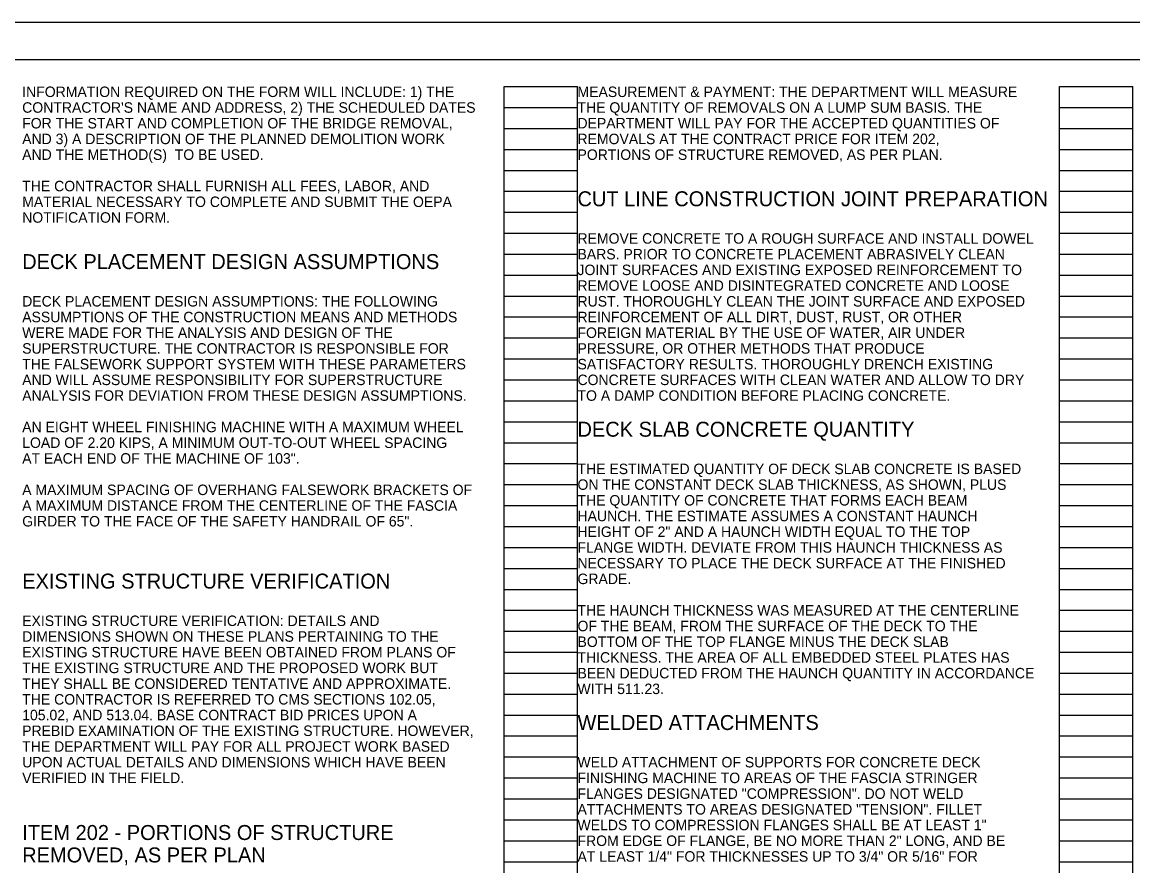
# Model space of a CAD drawing. Extents: x -51.6 to 45.5, y -38.3 to 35.3.
# Drawn here: x 10.32 to 25.16, y 10.73 to 22 of the extents above; entities that cross this region are included whole.
import ezdxf

# ---------------------------------------------------------------- set-up
doc = ezdxf.new("R2010")
doc.units = 0
for name, color, linetype in [('SH_Border', 7, 'Continuous'), ('SH_Cut_Line', 7, 'Continuous'), ('SH_Data', 7, 'Continuous'), ('SH_Text', 7, 'Continuous')]:
    doc.layers.add(name, color=color, linetype=linetype)

msp = doc.modelspace()

# ---------------------------------------------------------------- linework, layer by layer
at = {"layer": 'SH_Border'}
msp.add_lwpolyline([(2, 21.5), (33.5, 21.5), (33.5, 0.5), (2, 0.5)], close=True, dxfattribs=at)
at = {"layer": 'SH_Cut_Line'}
msp.add_lwpolyline([(0, 22), (34, 22), (34, 0), (0, 0)], close=True, dxfattribs=at)
at = {"layer": 'SH_Data'}
for p, q in [((16.76, 0.98), (16.76, 21.14)), ((16.76, 21.14), (17.74, 21.14)), ((17.74, 0.98), (17.74, 21.14)), ((24.18, 0.98), (24.18, 21.14)), ((24.18, 21.14), (25.16, 21.14)), ((25.16, 0.98), (25.16, 21.14)), ((16.76, 20.86), (17.74, 20.86)), ((24.18, 20.86), (25.16, 20.86)), ((16.76, 20.58), (17.74, 20.58)), ((24.18, 20.58), (25.16, 20.58)), ((16.76, 20.3), (17.74, 20.3)), ((24.18, 20.3), (25.16, 20.3)), ((16.76, 20.02), (17.74, 20.02)), ((24.18, 20.02), (25.16, 20.02)), ((16.76, 19.74), (17.74, 19.74)), ((24.18, 19.74), (25.16, 19.74)), ((16.76, 19.46), (17.74, 19.46)), ((24.18, 19.46), (25.16, 19.46)), ((16.76, 19.18), (17.74, 19.18)), ((24.18, 19.18), (25.16, 19.18)), ((16.76, 18.9), (17.74, 18.9)), ((24.18, 18.9), (25.16, 18.9)), ((16.76, 18.62), (17.74, 18.62)), ((24.18, 18.62), (25.16, 18.62)), ((16.76, 18.34), (17.74, 18.34)), ((24.18, 18.34), (25.16, 18.34)), ((16.76, 18.06), (17.74, 18.06)), ((24.18, 18.06), (25.16, 18.06)), ((16.76, 17.78), (17.74, 17.78)), ((24.18, 17.78), (25.16, 17.78)), ((16.76, 17.5), (17.74, 17.5)), ((24.18, 17.5), (25.16, 17.5)), ((16.76, 17.22), (17.74, 17.22)), ((24.18, 17.22), (25.16, 17.22)), ((16.76, 16.94), (17.74, 16.94)), ((24.18, 16.94), (25.16, 16.94)), ((16.76, 16.66), (17.74, 16.66)), ((24.18, 16.66), (25.16, 16.66)), ((16.76, 16.38), (17.74, 16.38)), ((24.18, 16.38), (25.16, 16.38)), ((16.76, 16.1), (17.74, 16.1)), ((24.18, 16.1), (25.16, 16.1)), ((16.76, 15.82), (17.74, 15.82)), ((24.18, 15.82), (25.16, 15.82)), ((16.76, 15.54), (17.74, 15.54)), ((24.18, 15.54), (25.16, 15.54)), ((16.76, 15.26), (17.74, 15.26)), ((24.18, 15.26), (25.16, 15.26)), ((16.76, 14.98), (17.74, 14.98)), ((24.18, 14.98), (25.16, 14.98)), ((16.76, 14.7), (17.74, 14.7)), ((24.18, 14.7), (25.16, 14.7)), ((16.76, 14.42), (17.74, 14.42)), ((24.18, 14.42), (25.16, 14.42)), ((16.76, 14.14), (17.74, 14.14)), ((24.18, 14.14), (25.16, 14.14)), ((16.76, 13.86), (17.74, 13.86)), ((24.18, 13.86), (25.16, 13.86)), ((16.76, 13.58), (17.74, 13.58)), ((24.18, 13.58), (25.16, 13.58)), ((16.76, 13.3), (17.74, 13.3)), ((24.18, 13.3), (25.16, 13.3)), ((16.76, 13.02), (17.74, 13.02)), ((24.18, 13.02), (25.16, 13.02)), ((16.76, 12.74), (17.74, 12.74)), ((24.18, 12.74), (25.16, 12.74)), ((16.76, 12.46), (17.74, 12.46)), ((24.18, 12.46), (25.16, 12.46)), ((16.76, 12.18), (17.74, 12.18)), ((24.18, 12.18), (25.16, 12.18)), ((16.76, 11.9), (17.74, 11.9)), ((24.18, 11.9), (25.16, 11.9)), ((16.76, 11.62), (17.74, 11.62)), ((24.18, 11.62), (25.16, 11.62)), ((16.76, 11.34), (17.74, 11.34)), ((24.18, 11.34), (25.16, 11.34)), ((16.76, 11.06), (17.74, 11.06)), ((24.18, 11.06), (25.16, 11.06)), ((16.76, 10.78), (17.74, 10.78)), ((24.18, 10.78), (25.16, 10.78))]:
    msp.add_line(p, q, dxfattribs=at)

# ---------------------------------------------------------------- texts
at = {"layer": 'SH_Text'}
for s, height, p in [('INFORMATION REQUIRED ON THE FORM WILL INCLUDE: 1) THE ', 0.14, (10.32, 21)), ('MEASUREMENT & PAYMENT: THE DEPARTMENT WILL MEASURE ', 0.14, (17.74, 21)), ("CONTRACTOR'S NAME AND ADDRESS, 2) THE SCHEDULED DATES ", 0.14, (10.32, 20.79)), ('THE QUANTITY OF REMOVALS ON A LUMP SUM BASIS. THE ', 0.14, (17.74, 20.79)), ('FOR THE START AND COMPLETION OF THE BRIDGE REMOVAL, ', 0.14, (10.32, 20.58)), ('DEPARTMENT WILL PAY FOR THE ACCEPTED QUANTITIES OF ', 0.14, (17.74, 20.58)), ('AND 3) A DESCRIPTION OF THE PLANNED DEMOLITION WORK ', 0.14, (10.32, 20.37)), ('REMOVALS AT THE CONTRACT PRICE FOR ITEM 202, ', 0.14, (17.74, 20.37)), ('AND THE METHOD(S)  TO BE USED.', 0.14, (10.32, 20.16)), ('PORTIONS OF STRUCTURE REMOVED, AS PER PLAN.', 0.14, (17.74, 20.16)), ('THE CONTRACTOR SHALL FURNISH ALL FEES, LABOR, AND ', 0.14, (10.32, 19.74)), ('CUT LINE CONSTRUCTION JOINT PREPARATION', 0.2, (17.74, 19.54)), ('MATERIAL NECESSARY TO COMPLETE AND SUBMIT THE OEPA ', 0.14, (10.32, 19.53)), ('NOTIFICATION FORM.', 0.14, (10.32, 19.32)), ('REMOVE CONCRETE TO A ROUGH SURFACE AND INSTALL DOWEL ', 0.14, (17.74, 19.04)), ('DECK PLACEMENT DESIGN ASSUMPTIONS', 0.2, (10.32, 18.7)), ('BARS. PRIOR TO CONCRETE PLACEMENT ABRASIVELY CLEAN ', 0.14, (17.74, 18.83)), ('JOINT SURFACES AND EXISTING EXPOSED REINFORCEMENT TO ', 0.14, (17.74, 18.62)), ('REMOVE LOOSE AND DISINTEGRATED CONCRETE AND LOOSE ', 0.14, (17.74, 18.41)), ('DECK PLACEMENT DESIGN ASSUMPTIONS: THE FOLLOWING ', 0.14, (10.32, 18.2)), ('RUST. THOROUGHLY CLEAN THE JOINT SURFACE AND EXPOSED ', 0.14, (17.74, 18.2)), ('ASSUMPTIONS OF THE CONSTRUCTION MEANS AND METHODS ', 0.14, (10.32, 17.99)), ('REINFORCEMENT OF ALL DIRT, DUST, RUST, OR OTHER ', 0.14, (17.74, 17.99)), ('WERE MADE FOR THE ANALYSIS AND DESIGN OF THE ', 0.14, (10.32, 17.78)), ('FOREIGN MATERIAL BY THE USE OF WATER, AIR UNDER ', 0.14, (17.74, 17.78)), ('SUPERSTRUCTURE. THE CONTRACTOR IS RESPONSIBLE FOR ', 0.14, (10.32, 17.57)), ('PRESSURE, OR OTHER METHODS THAT PRODUCE ', 0.14, (17.74, 17.57)), ('THE FALSEWORK SUPPORT SYSTEM WITH THESE PARAMETERS ', 0.14, (10.32, 17.36)), ('SATISFACTORY RESULTS. THOROUGHLY DRENCH EXISTING ', 0.14, (17.74, 17.36)), ('AND WILL ASSUME RESPONSIBILITY FOR SUPERSTRUCTURE ', 0.14, (10.32, 17.15)), ('CONCRETE SURFACES WITH CLEAN WATER AND ALLOW TO DRY ', 0.14, (17.74, 17.15)), ('ANALYSIS FOR DEVIATION FROM THESE DESIGN ASSUMPTIONS.', 0.14, (10.32, 16.94)), ('TO A DAMP CONDITION BEFORE PLACING CONCRETE.', 0.14, (17.74, 16.94)), ('AN EIGHT WHEEL FINISHING MACHINE WITH A MAXIMUM WHEEL ', 0.14, (10.32, 16.52)), ('DECK SLAB CONCRETE QUANTITY', 0.2, (17.74, 16.46)), ('LOAD OF 2.20 KIPS, A MINIMUM OUT-TO-OUT WHEEL SPACING ', 0.14, (10.32, 16.31)), ('AT EACH END OF THE MACHINE OF 103".', 0.14, (10.32, 16.1)), ('THE ESTIMATED QUANTITY OF DECK SLAB CONCRETE IS BASED ', 0.14, (17.74, 15.96)), ('ON THE CONSTANT DECK SLAB THICKNESS, AS SHOWN, PLUS ', 0.14, (17.74, 15.75)), ('A MAXIMUM SPACING OF OVERHANG FALSEWORK BRACKETS OF ', 0.14, (10.32, 15.68)), ('A MAXIMUM DISTANCE FROM THE CENTERLINE OF THE FASCIA ', 0.14, (10.32, 15.47)), ('THE QUANTITY OF CONCRETE THAT FORMS EACH BEAM ', 0.14, (17.74, 15.54)), ('HAUNCH. THE ESTIMATE ASSUMES A CONSTANT HAUNCH ', 0.14, (17.74, 15.33)), ('GIRDER TO THE FACE OF THE SAFETY HANDRAIL OF 65".', 0.14, (10.32, 15.26)), ('HEIGHT OF 2" AND A HAUNCH WIDTH EQUAL TO THE TOP ', 0.14, (17.74, 15.12)), ('FLANGE WIDTH. DEVIATE FROM THIS HAUNCH THICKNESS AS ', 0.14, (17.74, 14.91)), ('NECESSARY TO PLACE THE DECK SURFACE AT THE FINISHED ', 0.14, (17.74, 14.7)), ('EXISTING STRUCTURE VERIFICATION', 0.2, (10.32, 14.43)), ('GRADE. ', 0.14, (17.74, 14.49)), ('THE HAUNCH THICKNESS WAS MEASURED AT THE CENTERLINE ', 0.14, (17.74, 14.07)), ('EXISTING STRUCTURE VERIFICATION: DETAILS AND ', 0.14, (10.32, 13.93)), ('OF THE BEAM, FROM THE SURFACE OF THE DECK TO THE ', 0.14, (17.74, 13.86)), ('DIMENSIONS SHOWN ON THESE PLANS PERTAINING TO THE ', 0.14, (10.32, 13.72)), ('BOTTOM OF THE TOP FLANGE MINUS THE DECK SLAB ', 0.14, (17.74, 13.65)), ('EXISTING STRUCTURE HAVE BEEN OBTAINED FROM PLANS OF ', 0.14, (10.32, 13.51)), ('THICKNESS. THE AREA OF ALL EMBEDDED STEEL PLATES HAS ', 0.14, (17.74, 13.44)), ('THE EXISTING STRUCTURE AND THE PROPOSED WORK BUT ', 0.14, (10.32, 13.3)), ('BEEN DEDUCTED FROM THE HAUNCH QUANTITY IN ACCORDANCE ', 0.14, (17.74, 13.23)), ('THEY SHALL BE CONSIDERED TENTATIVE AND APPROXIMATE. ', 0.14, (10.32, 13.09)), ('WITH 511.23.', 0.14, (17.74, 13.02)), ('THE CONTRACTOR IS REFERRED TO CMS SECTIONS 102.05, ', 0.14, (10.32, 12.88)), ('105.02, AND 513.04. BASE CONTRACT BID PRICES UPON A ', 0.14, (10.32, 12.67)), ('WELDED ATTACHMENTS', 0.2, (17.74, 12.54)), ('PREBID EXAMINATION OF THE EXISTING STRUCTURE. HOWEVER, ', 0.14, (10.32, 12.46)), ('THE DEPARTMENT WILL PAY FOR ALL PROJECT WORK BASED ', 0.14, (10.32, 12.25)), ('UPON ACTUAL DETAILS AND DIMENSIONS WHICH HAVE BEEN ', 0.14, (10.32, 12.04)), ('WELD ATTACHMENT OF SUPPORTS FOR CONCRETE DECK ', 0.14, (17.74, 12.04)), ('VERIFIED IN THE FIELD.', 0.14, (10.32, 11.83)), ('FINISHING MACHINE TO AREAS OF THE FASCIA STRINGER ', 0.14, (17.74, 11.83)), ('FLANGES DESIGNATED "COMPRESSION". DO NOT WELD ', 0.14, (17.74, 11.62)), ('ATTACHMENTS TO AREAS DESIGNATED "TENSION". FILLET ', 0.14, (17.74, 11.41)), ('WELDS TO COMPRESSION FLANGES SHALL BE AT LEAST 1" ', 0.14, (17.74, 11.2)), ('ITEM 202 - PORTIONS OF STRUCTURE ', 0.2, (10.32, 11.07)), ('FROM EDGE OF FLANGE, BE NO MORE THAN 2" LONG, AND BE ', 0.14, (17.74, 10.99)), ('REMOVED, AS PER PLAN', 0.2, (10.32, 10.77)), ('AT LEAST 1/4" FOR THICKNESSES UP TO 3/4" OR 5/16" FOR ', 0.14, (17.74, 10.78))]:
    msp.add_text(s, height=height, dxfattribs=at).set_placement(p)

doc.saveas('drawing.dxf')
